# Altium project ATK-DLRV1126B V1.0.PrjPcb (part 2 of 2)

## Sheet 11_ATK_RV1126B_TYPEC_USB30.SchDoc
size A4; Author: ALIENTEK; Revision: 0; SheetNumber: 11; SheetTotal: 13; Version: V1.0; SheetSize: A4
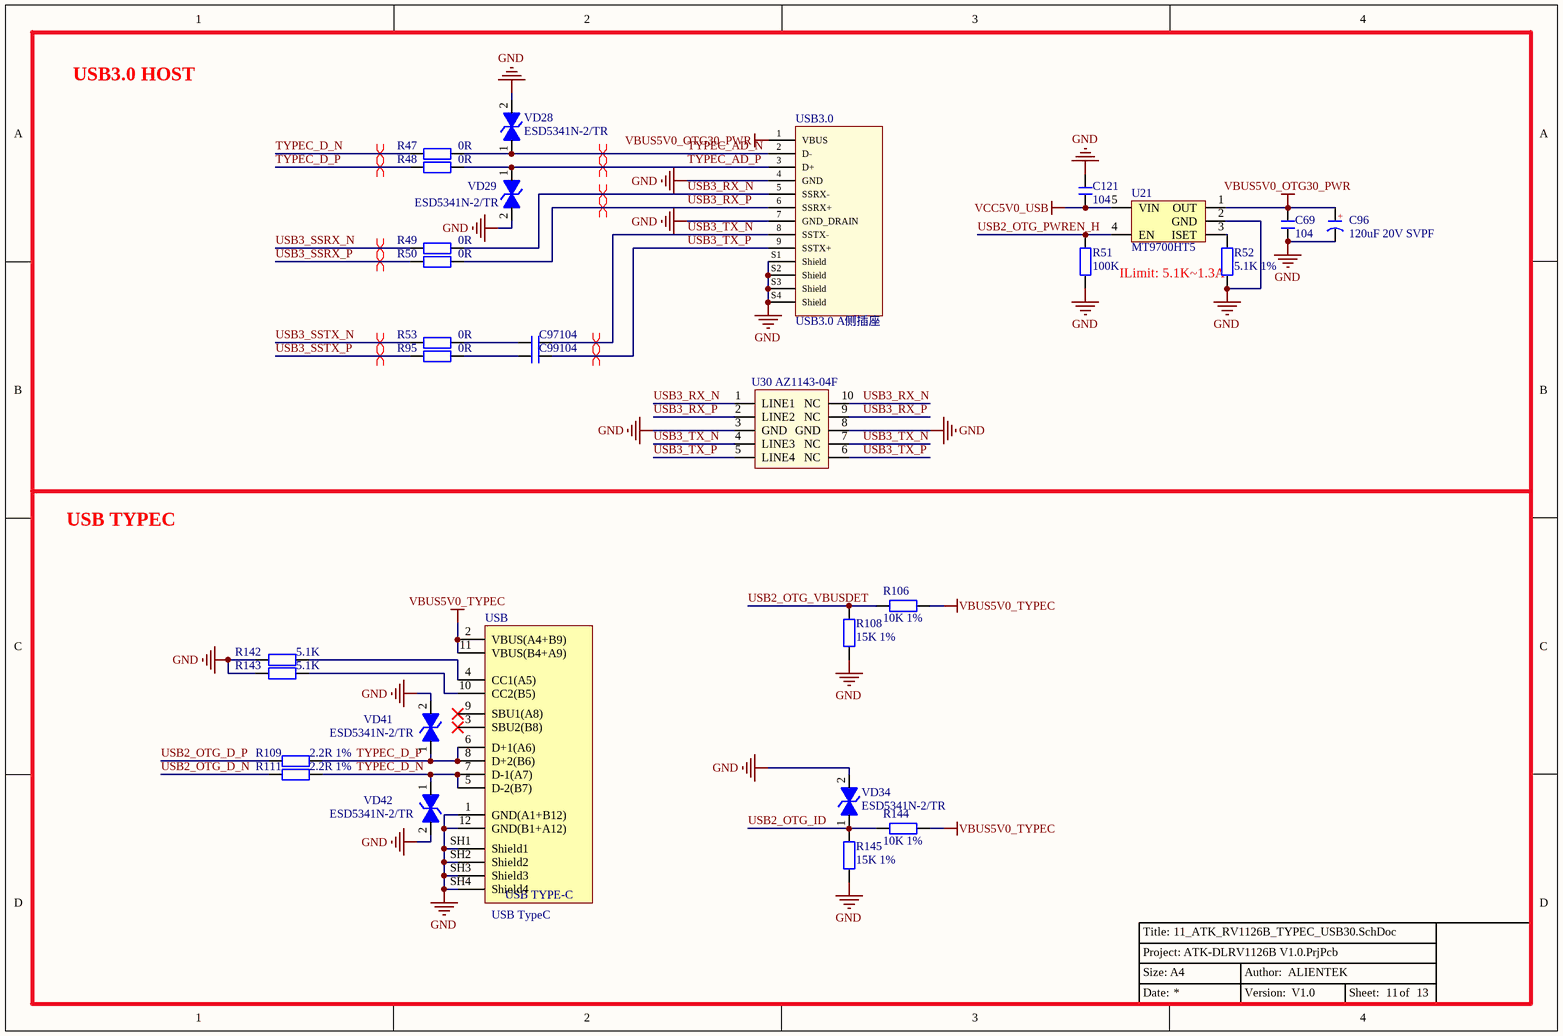
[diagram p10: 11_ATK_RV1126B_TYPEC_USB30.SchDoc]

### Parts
C69  104  [C 0402]
C96  120uF 20V SVPF  [CM D(6.3*7.7)]
C97  104  [C 0402]
C99  104  [C 0402]
C121  104  [C 0402]
R47  0R  [R 0402]
R48  0R  [R 0402]
R49  0R  [R 0402]
R50  0R  [R 0402]
R51  100K  [R 0402]
R52  5.1K 1%  [R 0402]
R53  0R  [R 0402]
R95  0R  [R 0402]
R106  10K 1%  [R 0402]
R108  15K 1%  [R 0402]
R109  2.2R 1%  [R 0402]
R111  2.2R 1%  [R 0402]
R142  5.1K  [R 0402]
R143  5.1K  [R 0402]
R144  10K 1%  [R 0402]
R145  15K 1%  [R 0402]
U21  MT9700HT5  [SOT23-5N]
U30  AZ1143-04F  [DFN2510P10E]
USB  USB TypeC  [USB2.0-TYPE-C-16P]
USB3.0  USB3.0 A侧插座  [USB3.0 A侧插]
VD28  ESD5341N-2/TR  [ESD0402]
VD29  ESD5341N-2/TR  [ESD0402]
VD34  ESD5341N-2/TR  [ESD0402]
VD41  ESD5341N-2/TR  [ESD0402]
VD42  ESD5341N-2/TR  [ESD0402]

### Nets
GND: C69.2 C96.2(K) C121.1 R51.2 R52.2 R108.2 R142.1 R143.1 R145.2 U21.2(GND) U30.3(GND) U30.8(GND) USB.1(GND(A1+B12)) USB.12(GND(B1+A12)) USB.SH1(Shield1) USB.SH2(Shield2) USB.SH3(Shield3) USB.SH4(Shield4) USB3.0.4(GND) USB3.0.7(GND_DRAIN) USB3.0.S1(Shield) USB3.0.S2(Shield) USB3.0.S3(Shield) USB3.0.S4(Shield) VD28.2 VD29.2 VD34.2 VD41.2 VD42.2
VBUS5V0_OTG30_PWR: C69.1 C96.1(A) U21.1(OUT) USB3.0.1(VBUS)
VBUS5V0_TYPEC: R106.1 R144.1 USB.2(VBUS(A4+B9)) USB.11(VBUS(B4+A9))
VCC5V0_USB: C121.2 U21.5(VIN)
TYPEC_AD_N: R47.1 USB3.0.2(D-) VD28.1
TYPEC_AD_P: R48.1 USB3.0.3(D+) VD29.1
TYPEC_D_N: R47.2 R111.1 USB.5(D-2(B7)) USB.7(D-1(A7)) VD42.1
TYPEC_D_P: R48.2 R109.1 USB.6(D+1(A6)) USB.8(D+2(B6)) VD41.1
USB2_OTG_D_N: R111.2
USB2_OTG_D_P: R109.2
USB2_OTG_ID: R144.2 R145.1 VD34.1
USB2_OTG_PWREN_H: R51.1 U21.4(EN)  [project net GPIO5_A7]
USB2_OTG_VBUSDET: R106.2 R108.1
USB3_RX_N: R49.1 U30.1(LINE1) U30.10(NC) USB3.0.5(SSRX-)
USB3_RX_P: R50.1 U30.2(LINE2) U30.9(NC) USB3.0.6(SSRX+)
USB3_SSRX_N: R49.2
USB3_SSRX_P: R50.2
USB3_SSTX_N: R53.2
USB3_SSTX_P: R95.2
USB3_TX_N: C97.2 U30.4(LINE3) U30.7(NC) USB3.0.8(SSTX-)
USB3_TX_P: C99.2 U30.5(LINE4) U30.6(NC) USB3.0.9(SSTX+)
NetC97_1: C97.1 R53.1
NetC99_1: C99.1 R95.1
NetR52_1: R52.1 U21.3(ISET)
NetR142_2: R142.2 USB.4(CC1(A5))
NetR143_2: R143.2 USB.10(CC2(B5))

Not connected (* = marked no-connect by the designer): USB 3(SBU2(B8))* 9(SBU1(A8))*

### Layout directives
differential pair: TYPEC_AD_N, TYPEC_AD_P, TYPEC_D_N, TYPEC_D_P, USB3_RX_N, USB3_RX_P, USB3_SSRX_N, USB3_SSRX_P, USB3_SSTX_N, USB3_SSTX_P, USB3_TX_N, USB3_TX_P

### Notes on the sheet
- USB3.0 HOST
- (near R52) ILimit: 5.1K
  .3A
- USB TYPEC

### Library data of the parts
C69 C97 C99 C121 = C: 无极性贴片电容; 版权归属: 源创客
C96 = C-CM: 贴片电解电容; 版权归属: 源创客
R47-R53 R95 R106 R108 R109 R111 R142-R145 = R: 贴片电阻; BOM名称: 电阻; 版权归属: 正点原子
U21 = MT9700HT5: 功率开关(5.5V-2A); BOM名称: 稳压芯片; 版权归属: 正点原子
U30 = AZ1143-04F: ESD保护二极管阵列
USB = USB Type-C: 12P TypeC 母座; 版权归属: 正点原子; Parameter: 接口器件
USB3.0 = USB3.0 A侧插
VD28 VD29 VD34 VD41 VD42 = ESD5341N: ESD二极管-单向

## Sheet 12_ATK_RV1126B_CSI_DSI.SchDoc
size A4; Author: ALIENTEK; Revision: 0; SheetNumber: 12; SheetTotal: 13; Version: V1.0; SheetSize: A4
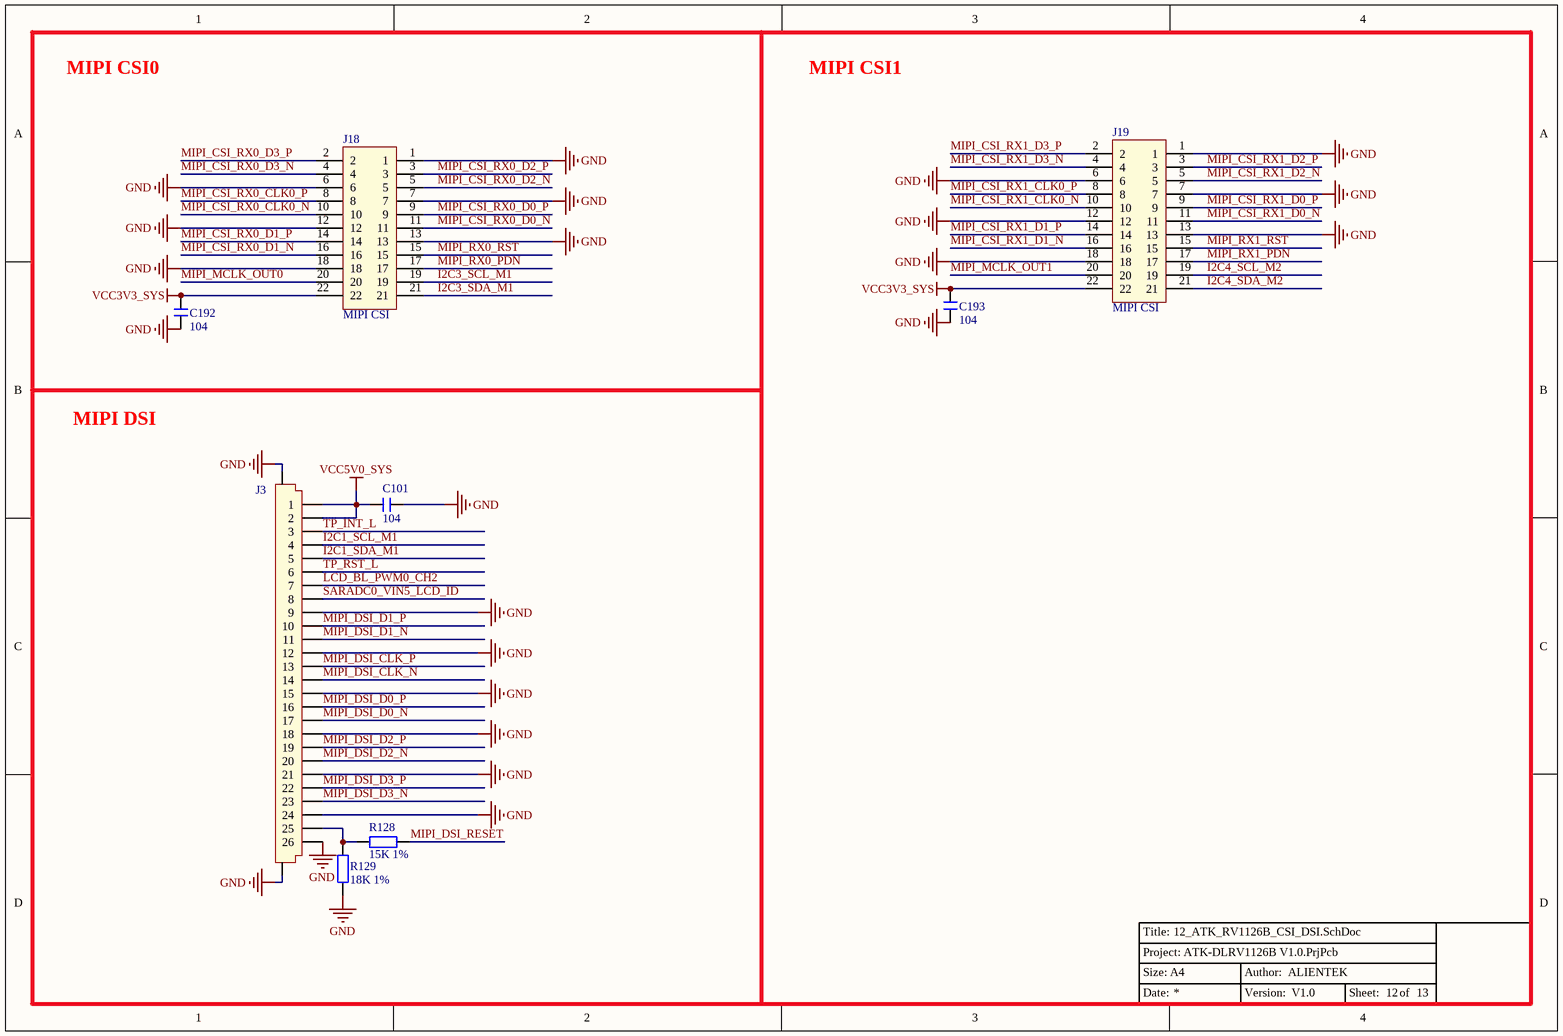
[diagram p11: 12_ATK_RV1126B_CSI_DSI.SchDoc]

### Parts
C101  104  [C 0402]
C192  104  [C 0402]
C193  104  [C 0402]
J3  FPC0.5-26P  [FPC 0.5 26P V-S]  (value not drawn)
J18  MIPI CSI  [HEADER 2.0 2X11P]
J19  MIPI CSI  [HEADER 2.0 2X11P]
R128  15K 1%  [R 0402]
R129  18K 1%  [R 0402]

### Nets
GND: C101.1 C192.1 C193.1 J3.0 J3.9 J3.12 J3.15 J3.18 J3.21 J3.24 J3.26 J18.1 J18.6 J18.7 J18.12 J18.13 J18.18 J19.1 J19.6 J19.7 J19.12 J19.13 J19.18 R129.1
VCC3V3_SYS: C192.2 C193.2 J18.22 J19.22
VCC5V0_SYS: C101.2 J3.1 J3.2
I2C1_SCL_M1: J3.4  [project net GPIO3_A2]
I2C1_SDA_M1: J3.5  [project net GPIO3_A3]
I2C3_SCL_M1: J18.19  [project net GPIO4_A4]
I2C3_SDA_M1: J18.21  [project net GPIO4_A5]
I2C4_SCL_M2: J19.19  [project net GPIO4_A7]
I2C4_SDA_M2: J19.21  [project net GPIO4_A6]
LCD_BL_PWM0_CH2: J3.7  [project net GPIO0_C6]
MIPI_CSI_RX0_CLK0_N: J18.10
MIPI_CSI_RX0_CLK0_P: J18.8
MIPI_CSI_RX0_D0_N: J18.11
MIPI_CSI_RX0_D0_P: J18.9
MIPI_CSI_RX0_D1_N: J18.16
MIPI_CSI_RX0_D1_P: J18.14
MIPI_CSI_RX0_D2_N: J18.5
MIPI_CSI_RX0_D2_P: J18.3
MIPI_CSI_RX0_D3_N: J18.4
MIPI_CSI_RX0_D3_P: J18.2
MIPI_CSI_RX1_CLK0_N: J19.10
MIPI_CSI_RX1_CLK0_P: J19.8
MIPI_CSI_RX1_D0_N: J19.11
MIPI_CSI_RX1_D0_P: J19.9
MIPI_CSI_RX1_D1_N: J19.16
MIPI_CSI_RX1_D1_P: J19.14
MIPI_CSI_RX1_D2_N: J19.5
MIPI_CSI_RX1_D2_P: J19.3
MIPI_CSI_RX1_D3_N: J19.4
MIPI_CSI_RX1_D3_P: J19.2
MIPI_DSI_CLK_N: J3.14
MIPI_DSI_CLK_P: J3.13
MIPI_DSI_D0_N: J3.17
MIPI_DSI_D0_P: J3.16
MIPI_DSI_D1_N: J3.11
MIPI_DSI_D1_P: J3.10
MIPI_DSI_D2_N: J3.20
MIPI_DSI_D2_P: J3.19
MIPI_DSI_D3_N: J3.23
MIPI_DSI_D3_P: J3.22
MIPI_DSI_RESET: R128.2  [project net GPIO7_A7]
MIPI_MCLK_OUT0: J18.20  [project net GPIO4_B1]
MIPI_MCLK_OUT1: J19.20  [project net GPIO4_B0]
MIPI_RX0_PDN: J18.17  [project net GPIO4_A2]
MIPI_RX0_RST: J18.15  [project net GPIO4_A0]
MIPI_RX1_PDN: J19.17  [project net GPIO4_A3]
MIPI_RX1_RST: J19.15  [project net GPIO4_A1]
SARADC0_VIN5_LCD_ID: J3.8
TP_INT_L: J3.3  [project net GPIO3_B3]
TP_RST_L: J3.6  [project net GPIO0_B2]
NetJ3_25: J3.25 R128.1 R129.2

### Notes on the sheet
- MIPI CSI0
- MIPI CSI1
- MIPI DSI

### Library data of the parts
C101 C192 C193 = C: 无极性贴片电容; 版权归属: 正点原子
J3 = FPC-26P: FPC连接器; 版权归属: 正点原子; Parameter: 接口器件
J18 J19 = HEADER 2X11P
R128 R129 = R: 贴片电阻; 版权归属: 正点原子

## Sheet 13_ATK_RV1126B_WIFI_CIF_PIN.SchDoc
size A4; Author: ALIENTEK; Revision: 0; SheetNumber: 13; SheetTotal: 13; Version: V1.0; SheetSize: A4
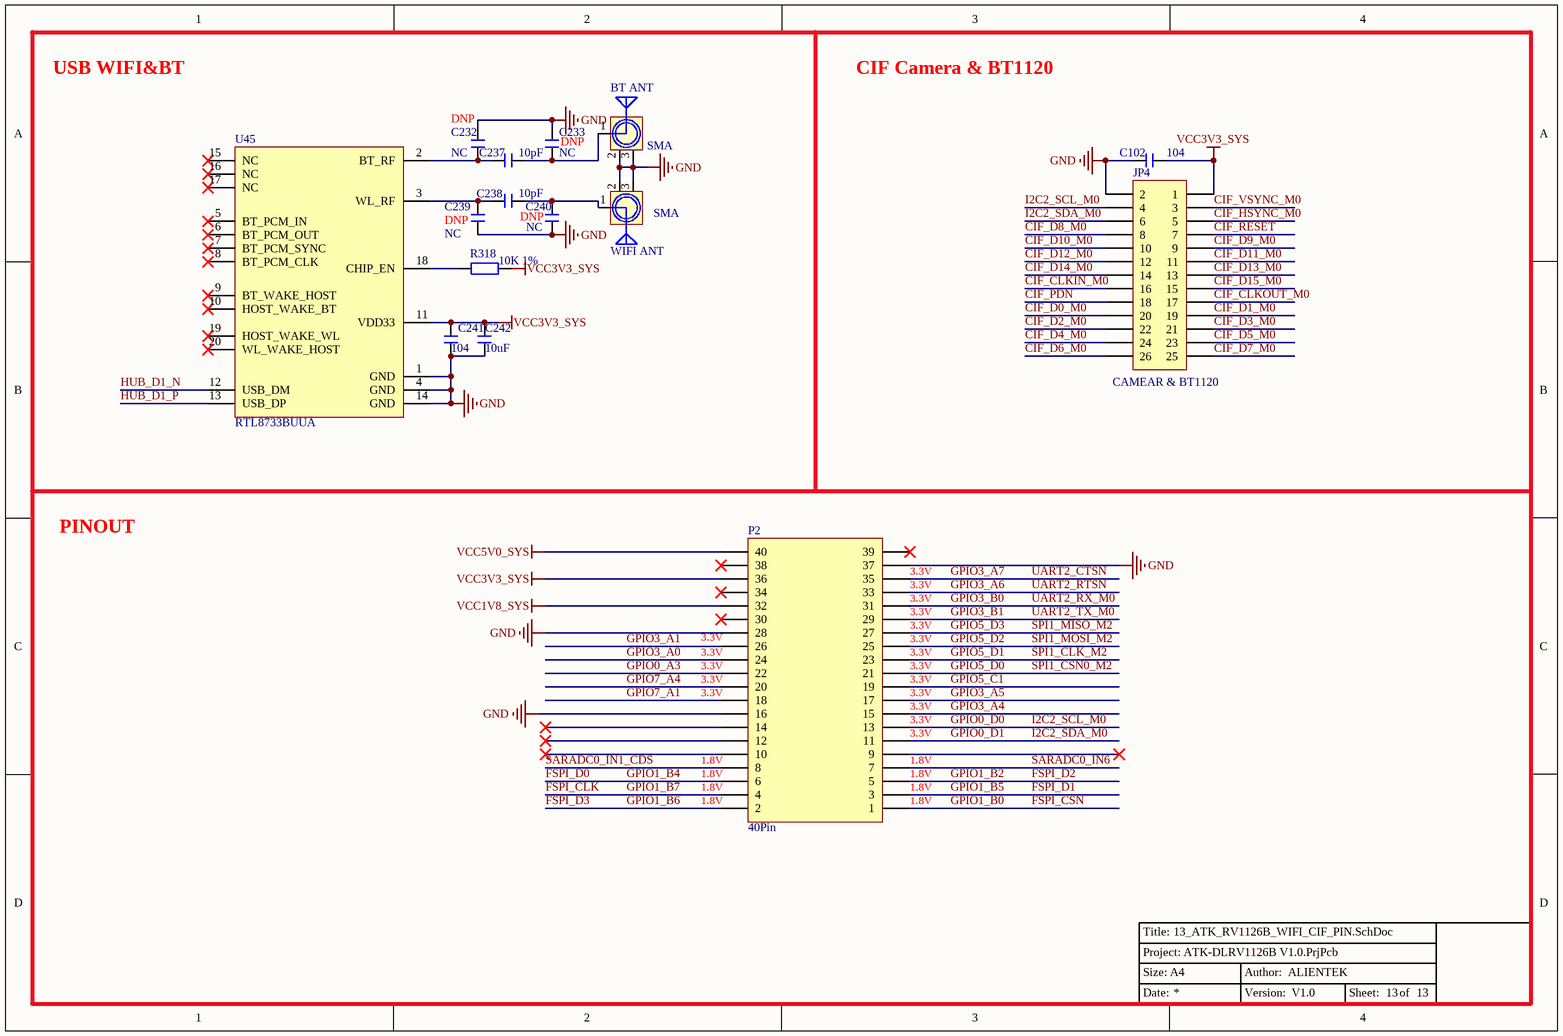
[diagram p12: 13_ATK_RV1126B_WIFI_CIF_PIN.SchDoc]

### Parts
BT_ANT  SMA  [SMA-KWE]
C102  104  [C 0402]
C232  NC  [C 0603]
C233  NC  [C 0603]
C237  10pF  [C 0402]
C238  10pF  [C 0402]
C239  NC  [C 0603]
C240  NC  [C 0603]
C241  104  [C 0402]
C242  10uF  [C 0603]
JP4  CAMEAR & BT1120  [Header 2.54 2X13P]
P2  40Pin  [HDR-20X2]
R318  10K 1%  [R 0402]
U45  RTL8733BUUA  [RTL8733BUBUA]
WIFI_ANT  SMA  [SMA-KWE]

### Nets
GND: BT_ANT.2(GND) BT_ANT.3(GND) C102.1 C232.1 C233.1 C239.2 C240.2 C241.2 C242.2 JP4.2 P2.16 P2.28 P2.37 U45.1(GND) U45.4(GND) U45.14(GND) WIFI_ANT.2(GND) WIFI_ANT.3(GND)
VCC1V8_SYS: P2.32
VCC3V3_SYS: C102.2 C241.1 C242.1 JP4.1 P2.36 R318.1 U45.11(VDD33)
VCC5V0_SYS: P2.40
CIF_CLKIN_M0: JP4.16
CIF_CLKOUT_M0: JP4.17
CIF_D0_M0: JP4.20
CIF_D1_M0: JP4.19
CIF_D2_M0: JP4.22
CIF_D3_M0: JP4.21
CIF_D4_M0: JP4.24
CIF_D5_M0: JP4.23
CIF_D6_M0: JP4.26
CIF_D7_M0: JP4.25
CIF_D8_M0: JP4.8
CIF_D9_M0: JP4.9
CIF_D10_M0: JP4.10
CIF_D11_M0: JP4.11
CIF_D12_M0: JP4.12
CIF_D13_M0: JP4.13
CIF_D14_M0: JP4.14
CIF_D15_M0: JP4.15
CIF_HSYNC_M0: JP4.5
CIF_PDN: JP4.18
CIF_RESET: JP4.7
CIF_VSYNC_M0: JP4.3
FSPI_CLK: P2.4  [also labelled GPIO1_B7]
FSPI_CSN: P2.1  [also labelled GPIO1_B0]
FSPI_D0: P2.6  [also labelled GPIO1_B4]
FSPI_D1: P2.3  [also labelled GPIO1_B5]
FSPI_D2: P2.5  [also labelled GPIO1_B2]
FSPI_D3: P2.2  [also labelled GPIO1_B6]
GPIO0_A3: P2.22
GPIO0_D0: JP4.4 P2.13  [also labelled I2C2_SCL_M0]
GPIO0_D1: JP4.6 P2.11  [also labelled I2C2_SDA_M0]
GPIO3_A0: P2.24
GPIO3_A1: P2.26
GPIO3_A4: P2.15
GPIO3_A5: P2.17
GPIO3_A6: P2.33  [also labelled UART2_RTSN]
GPIO3_A7: P2.35  [also labelled UART2_CTSN]
GPIO3_B0: P2.31  [also labelled UART2_RX_M0]
GPIO3_B1: P2.29  [also labelled UART2_TX_M0]
GPIO5_C1: P2.19  [project net CLK_OUT_ETHERNET]
GPIO5_D0: P2.21  [also labelled SPI1_CSN0_M2]  [project net GMAC_PTP_REFCLK]
GPIO5_D1: P2.23  [also labelled SPI1_CLK_M2]  [project net GMAC_PPSTRIG]
GPIO5_D2: P2.25  [also labelled SPI1_MOSI_M2]
GPIO5_D3: P2.27  [also labelled SPI1_MISO_M2]
GPIO7_A1: P2.18
GPIO7_A4: P2.20
HUB_D1_N: U45.12(USB_DM)
HUB_D1_P: U45.13(USB_DP)
SARADC0_IN1_CDS: P2.8
SARADC0_IN6: P2.7
NetBT_ANT_1: BT_ANT.1(ANT) C233.2 C237.1
NetC232_2: C232.2 C237.2 U45.2(BT_RF)
NetC238_1: C238.1 C240.1 WIFI_ANT.1(ANT)
NetC238_2: C238.2 C239.1 U45.3(WL_RF)
NetR318_2: R318.2 U45.18(CHIP_EN)

Not connected (* = marked no-connect by the designer): P2 9* 10* 12* 14* 30* 34* 38* 39*; U45 5(BT_PCM_IN)* 6(BT_PCM_OUT)* 7(BT_PCM_SYNC)* 8(BT_PCM_CLK)* 9(BT_WAKE_HOST)* 10(HOST_WAKE_BT)* 15(NC)* 16(NC)* 17(NC)* 19(HOST_WAKE_WL)* 20(WL_WAKE_HOST)*

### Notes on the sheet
- USB WIFI&BT
- CIF Camera & BT1120
- (near C232) DNP
- (near C233) DNP
- (near C239) DNP
- DNP
- PINOUT
- (near P2) 3.3V
- (near P2) 1.8V

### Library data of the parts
BT_ANT WIFI_ANT = SMA: SMA-2.4G射频天线接口; 版权归属: 正点原子
C102 C232 C233 C237-C242 = C: 无极性贴片电容; 版权归属: 源创客
JP4 = Header 13X2: Header, 13-Pin, Dual row
P2 = RPI40Pin
R318 = R: 贴片电阻; 版权归属: 正点原子

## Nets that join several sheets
GND: 02_ATK_RV1126B_Core_Board (55 pins), 03_ATK_RV1126B_Power_USB (67 pins), 04_ATK_RV1126B_4G_USBHUB (47 pins), 05_ATK_RV1126B_DEVICE (31 pins), 06_ATK_RV1126B_ES8390_Audio (49 pins), 08_ATK_RV1126B_RS485_CAN (21 pins), 09_ATK_RV1126B_RGMII_NET (35 pins), 10_ATK_RV1126B_FEPHY_NET_OPT (18 pins), 11_ATK_RV1126B_TYPEC_USB30 (29 pins), 12_ATK_RV1126B_CSI_DSI (24 pins), 13_ATK_RV1126B_WIFI_CIF_PIN (18 pins)
VBAT: 03_ATK_RV1126B_Power_USB (BAT.1 C2.1 L1.2), 05_ATK_RV1126B_DEVICE (L10.2)
VBAT_RTC: 02_ATK_RV1126B_Core_Board (U1.A114), 03_ATK_RV1126B_Power_USB (L1.1)
VCC1V8_SYS: 03_ATK_RV1126B_Power_USB (C26.1 C27.1 L3.2 R27.2), 05_ATK_RV1126B_DEVICE (5 pins), 13_ATK_RV1126B_WIFI_CIF_PIN (P2.32)
VCC3V3_SYS: 03_ATK_RV1126B_Power_USB (12 pins), 05_ATK_RV1126B_DEVICE (12 pins), 08_ATK_RV1126B_RS485_CAN (18 pins), 09_ATK_RV1126B_RGMII_NET (L19.2 L20.2), 12_ATK_RV1126B_CSI_DSI (C192.2 C193.2 J18.22 J19.22), 13_ATK_RV1126B_WIFI_CIF_PIN (7 pins)
VCC5V0_SYS: 02_ATK_RV1126B_Core_Board (U1.A117 U1.A118 U1.A119 U1.A120), 03_ATK_RV1126B_Power_USB (8 pins), 06_ATK_RV1126B_ES8390_Audio (C14.1 L12.1 R11.1 U15.1), 08_ATK_RV1126B_RS485_CAN (5 pins), 12_ATK_RV1126B_CSI_DSI (C101.2 J3.1 J3.2), 13_ATK_RV1126B_WIFI_CIF_PIN (P2.40)
VCC5V0_USB: 03_ATK_RV1126B_Power_USB (5 pins), 04_ATK_RV1126B_4G_USBHUB (L6.2 USB_HOST1.1 USB_HOST2.1), 11_ATK_RV1126B_TYPEC_USB30 (C121.2 U21.5)
VCC12V_DCIN: 03_ATK_RV1126B_Power_USB (23 pins), 04_ATK_RV1126B_4G_USBHUB (C57.2 C58.2 R54.1 U10.3), 08_ATK_RV1126B_RS485_CAN (FAN.2)
CAN0_RXD: 02_ATK_RV1126B_Core_Board (U1.A94), 08_ATK_RV1126B_RS485_CAN (R23.2)
CAN0_TXD: 02_ATK_RV1126B_Core_Board (U1.A93), 08_ATK_RV1126B_RS485_CAN (R21.2)
CAN1_RXD: 02_ATK_RV1126B_Core_Board (U1.A90), 08_ATK_RV1126B_RS485_CAN (R45.2)
CAN1_TXD: 02_ATK_RV1126B_Core_Board (U1.A91), 08_ATK_RV1126B_RS485_CAN (R39.2)
CIF_CLKIN_M0: 02_ATK_RV1126B_Core_Board (U1.B5), 13_ATK_RV1126B_WIFI_CIF_PIN (JP4.16)
CIF_CLKOUT_M0: 02_ATK_RV1126B_Core_Board (U1.B3), 13_ATK_RV1126B_WIFI_CIF_PIN (JP4.17)
CIF_D0_M0: 02_ATK_RV1126B_Core_Board (U1.B22), 13_ATK_RV1126B_WIFI_CIF_PIN (JP4.20)
CIF_D1_M0: 02_ATK_RV1126B_Core_Board (U1.B21), 13_ATK_RV1126B_WIFI_CIF_PIN (JP4.19)
CIF_D2_M0: 02_ATK_RV1126B_Core_Board (U1.B20), 13_ATK_RV1126B_WIFI_CIF_PIN (JP4.22)
CIF_D3_M0: 02_ATK_RV1126B_Core_Board (U1.B19), 13_ATK_RV1126B_WIFI_CIF_PIN (JP4.21)
CIF_D4_M0: 02_ATK_RV1126B_Core_Board (U1.B18), 13_ATK_RV1126B_WIFI_CIF_PIN (JP4.24)
CIF_D5_M0: 02_ATK_RV1126B_Core_Board (U1.B17), 13_ATK_RV1126B_WIFI_CIF_PIN (JP4.23)
CIF_D6_M0: 02_ATK_RV1126B_Core_Board (U1.B16), 13_ATK_RV1126B_WIFI_CIF_PIN (JP4.26)
CIF_D7_M0: 02_ATK_RV1126B_Core_Board (U1.B15), 13_ATK_RV1126B_WIFI_CIF_PIN (JP4.25)
CIF_D8_M0: 02_ATK_RV1126B_Core_Board (U1.B14), 13_ATK_RV1126B_WIFI_CIF_PIN (JP4.8)
CIF_D9_M0: 02_ATK_RV1126B_Core_Board (U1.B13), 13_ATK_RV1126B_WIFI_CIF_PIN (JP4.9)
CIF_D10_M0: 02_ATK_RV1126B_Core_Board (U1.B12), 13_ATK_RV1126B_WIFI_CIF_PIN (JP4.10)
CIF_D11_M0: 02_ATK_RV1126B_Core_Board (U1.B11), 13_ATK_RV1126B_WIFI_CIF_PIN (JP4.11)
CIF_D12_M0: 02_ATK_RV1126B_Core_Board (U1.B10), 13_ATK_RV1126B_WIFI_CIF_PIN (JP4.12)
CIF_D13_M0: 02_ATK_RV1126B_Core_Board (U1.B9), 13_ATK_RV1126B_WIFI_CIF_PIN (JP4.13)
CIF_D14_M0: 02_ATK_RV1126B_Core_Board (U1.B8), 13_ATK_RV1126B_WIFI_CIF_PIN (JP4.14)
CIF_D15_M0: 02_ATK_RV1126B_Core_Board (U1.B7), 13_ATK_RV1126B_WIFI_CIF_PIN (JP4.15)
CIF_HSYNC_M0: 02_ATK_RV1126B_Core_Board (U1.B2), 13_ATK_RV1126B_WIFI_CIF_PIN (JP4.5)
CIF_PDN: 02_ATK_RV1126B_Core_Board (U1.B54), 13_ATK_RV1126B_WIFI_CIF_PIN (JP4.18)
CIF_RESET: 02_ATK_RV1126B_Core_Board (U1.A36), 13_ATK_RV1126B_WIFI_CIF_PIN (JP4.7)
CIF_VSYNC_M0: 02_ATK_RV1126B_Core_Board (U1.B6), 13_ATK_RV1126B_WIFI_CIF_PIN (JP4.3)
CLK_OUT_ETHERNET: 02_ATK_RV1126B_Core_Board (U1.A27), 13_ATK_RV1126B_WIFI_CIF_PIN (P2.19)
FSPI_CLK: 02_ATK_RV1126B_Core_Board (U1.A63), 13_ATK_RV1126B_WIFI_CIF_PIN (P2.4)
FSPI_CSN: 02_ATK_RV1126B_Core_Board (U1.A57), 13_ATK_RV1126B_WIFI_CIF_PIN (P2.1)
FSPI_D0: 02_ATK_RV1126B_Core_Board (U1.A62), 13_ATK_RV1126B_WIFI_CIF_PIN (P2.6)
FSPI_D1: 02_ATK_RV1126B_Core_Board (U1.A58), 13_ATK_RV1126B_WIFI_CIF_PIN (P2.3)
FSPI_D2: 02_ATK_RV1126B_Core_Board (U1.A59), 13_ATK_RV1126B_WIFI_CIF_PIN (P2.5)
FSPI_D3: 02_ATK_RV1126B_Core_Board (U1.A64), 13_ATK_RV1126B_WIFI_CIF_PIN (P2.2)
GMAC_INT: 02_ATK_RV1126B_Core_Board (U1.A8), 09_ATK_RV1126B_RGMII_NET (R46.1)
GMAC_MCLK: 02_ATK_RV1126B_Core_Board (U1.A7), 09_ATK_RV1126B_RGMII_NET (R191.1)
GMAC_MDC: 02_ATK_RV1126B_Core_Board (U1.A25), 09_ATK_RV1126B_RGMII_NET (R185.1)
GMAC_MDIO: 02_ATK_RV1126B_Core_Board (U1.A24), 09_ATK_RV1126B_RGMII_NET (R184.1)
GMAC_PPSCLK: 02_ATK_RV1126B_Core_Board (U1.A32), 08_ATK_RV1126B_RS485_CAN (P1.3)
GMAC_PPSTRIG: 02_ATK_RV1126B_Core_Board (U1.A29), 13_ATK_RV1126B_WIFI_CIF_PIN (P2.23)
GMAC_PTP_REFCLK: 02_ATK_RV1126B_Core_Board (U1.A28), 13_ATK_RV1126B_WIFI_CIF_PIN (P2.21)
GMAC_RST: 02_ATK_RV1126B_Core_Board (U1.A26), 09_ATK_RV1126B_RGMII_NET (R187.1)
GMAC_RXCLK: 02_ATK_RV1126B_Core_Board (U1.A10), 09_ATK_RV1126B_RGMII_NET (R177.2)
GMAC_RXCTL: 02_ATK_RV1126B_Core_Board (U1.A11), 09_ATK_RV1126B_RGMII_NET (R178.2)
GMAC_RXD0: 02_ATK_RV1126B_Core_Board (U1.A12), 09_ATK_RV1126B_RGMII_NET (R171.2)
GMAC_RXD1: 02_ATK_RV1126B_Core_Board (U1.A13), 09_ATK_RV1126B_RGMII_NET (R172.2)
GMAC_RXD2: 02_ATK_RV1126B_Core_Board (U1.A14), 09_ATK_RV1126B_RGMII_NET (R173.2)
GMAC_RXD3: 02_ATK_RV1126B_Core_Board (U1.A15), 09_ATK_RV1126B_RGMII_NET (R174.2)
GMAC_TXCLK: 02_ATK_RV1126B_Core_Board (U1.A17), 09_ATK_RV1126B_RGMII_NET (U23.20)
GMAC_TXCTL: 02_ATK_RV1126B_Core_Board (U1.A19), 09_ATK_RV1126B_RGMII_NET (U23.19)
GMAC_TXD0: 02_ATK_RV1126B_Core_Board (U1.A20), 09_ATK_RV1126B_RGMII_NET (U23.18)
GMAC_TXD1: 02_ATK_RV1126B_Core_Board (U1.A21), 09_ATK_RV1126B_RGMII_NET (U23.17)
GMAC_TXD2: 02_ATK_RV1126B_Core_Board (U1.A22), 09_ATK_RV1126B_RGMII_NET (U23.16)
GMAC_TXD3: 02_ATK_RV1126B_Core_Board (U1.A23), 09_ATK_RV1126B_RGMII_NET (U23.15)
GPIO0_A0: 02_ATK_RV1126B_Core_Board (U1.B50), 06_ATK_RV1126B_ES8390_Audio (R57.1 U13.1 U14.1)
GPIO0_A2: 02_ATK_RV1126B_Core_Board (U1.B51), 06_ATK_RV1126B_ES8390_Audio (R343.1)
GPIO0_A3: 02_ATK_RV1126B_Core_Board (U1.B61), 13_ATK_RV1126B_WIFI_CIF_PIN (P2.22)
GPIO0_A4: 02_ATK_RV1126B_Core_Board (U1.B57), 06_ATK_RV1126B_ES8390_Audio (C88.1 PHONE.7 R79.2 VD12.1)
GPIO0_A5: 02_ATK_RV1126B_Core_Board (U1.B31), 05_ATK_RV1126B_DEVICE (R92.2)
GPIO0_B0: 02_ATK_RV1126B_Core_Board (U1.B30), 05_ATK_RV1126B_DEVICE (R89.1)
GPIO0_B1: 02_ATK_RV1126B_Core_Board (U1.B59), 05_ATK_RV1126B_DEVICE (R17.2 U17.3)
GPIO0_B2: 02_ATK_RV1126B_Core_Board (U1.B60), 12_ATK_RV1126B_CSI_DSI (J3.6)
GPIO0_B3: 02_ATK_RV1126B_Core_Board (U1.B48), 03_ATK_RV1126B_Power_USB (R44.2)
GPIO0_B4: 02_ATK_RV1126B_Core_Board (U1.B49), 03_ATK_RV1126B_Power_USB (R81.2 R101.1)
GPIO0_C5: 02_ATK_RV1126B_Core_Board (U1.B53), 05_ATK_RV1126B_DEVICE (R113.2)
GPIO0_C6: 02_ATK_RV1126B_Core_Board (U1.B52), 12_ATK_RV1126B_CSI_DSI (J3.7)
GPIO0_D0: 02_ATK_RV1126B_Core_Board (U1.A103), 05_ATK_RV1126B_DEVICE (R100.2 U17.6), 13_ATK_RV1126B_WIFI_CIF_PIN (JP4.4 P2.13)
GPIO0_D1: 02_ATK_RV1126B_Core_Board (U1.A102), 05_ATK_RV1126B_DEVICE (R102.2 U17.5), 13_ATK_RV1126B_WIFI_CIF_PIN (JP4.6 P2.11)
GPIO2_A0: 02_ATK_RV1126B_Core_Board (U1.B33), 05_ATK_RV1126B_DEVICE (R90.2)
GPIO2_A1: 02_ATK_RV1126B_Core_Board (U1.B32), 05_ATK_RV1126B_DEVICE (R91.2)
GPIO2_A2: 02_ATK_RV1126B_Core_Board (U1.B37), 05_ATK_RV1126B_DEVICE (R83.2)
GPIO2_A3: 02_ATK_RV1126B_Core_Board (U1.B36), 05_ATK_RV1126B_DEVICE (R84.2)
GPIO2_A4: 02_ATK_RV1126B_Core_Board (U1.B34), 05_ATK_RV1126B_DEVICE (R86.2)
GPIO2_A5: 02_ATK_RV1126B_Core_Board (U1.B35), 05_ATK_RV1126B_DEVICE (R85.2)
GPIO3_A0: 02_ATK_RV1126B_Core_Board (U1.A46), 13_ATK_RV1126B_WIFI_CIF_PIN (P2.24)
GPIO3_A1: 02_ATK_RV1126B_Core_Board (U1.A47), 13_ATK_RV1126B_WIFI_CIF_PIN (P2.26)
GPIO3_A2: 02_ATK_RV1126B_Core_Board (U1.A45), 05_ATK_RV1126B_DEVICE (R15.2), 12_ATK_RV1126B_CSI_DSI (J3.4)
GPIO3_A3: 02_ATK_RV1126B_Core_Board (U1.A44), 05_ATK_RV1126B_DEVICE (R16.2), 12_ATK_RV1126B_CSI_DSI (J3.5)
GPIO3_A4: 02_ATK_RV1126B_Core_Board (U1.A49), 13_ATK_RV1126B_WIFI_CIF_PIN (P2.15)
GPIO3_A5: 02_ATK_RV1126B_Core_Board (U1.A48), 13_ATK_RV1126B_WIFI_CIF_PIN (P2.17)
GPIO3_A6: 02_ATK_RV1126B_Core_Board (U1.A53), 13_ATK_RV1126B_WIFI_CIF_PIN (P2.33)
GPIO3_A7: 02_ATK_RV1126B_Core_Board (U1.A54), 13_ATK_RV1126B_WIFI_CIF_PIN (P2.35)
GPIO3_B0: 02_ATK_RV1126B_Core_Board (U1.A55), 13_ATK_RV1126B_WIFI_CIF_PIN (P2.31)
GPIO3_B1: 02_ATK_RV1126B_Core_Board (U1.A56), 13_ATK_RV1126B_WIFI_CIF_PIN (P2.29)
GPIO3_B2: 02_ATK_RV1126B_Core_Board (U1.A51), 08_ATK_RV1126B_RS485_CAN (MOS3.2 R122.1 R127.2)
GPIO3_B3: 02_ATK_RV1126B_Core_Board (U1.A52), 12_ATK_RV1126B_CSI_DSI (J3.3)
GPIO3_B6: 02_ATK_RV1126B_Core_Board (U1.A97), 05_ATK_RV1126B_DEVICE (R12.2), 06_ATK_RV1126B_ES8390_Audio (R65.2)
GPIO3_B7: 02_ATK_RV1126B_Core_Board (U1.A96), 05_ATK_RV1126B_DEVICE (R13.2), 06_ATK_RV1126B_ES8390_Audio (R66.2)
GPIO4_A0: 02_ATK_RV1126B_Core_Board (U1.B119), 12_ATK_RV1126B_CSI_DSI (J18.15)
GPIO4_A1: 02_ATK_RV1126B_Core_Board (U1.B118), 12_ATK_RV1126B_CSI_DSI (J19.15)
GPIO4_A2: 02_ATK_RV1126B_Core_Board (U1.B114), 12_ATK_RV1126B_CSI_DSI (J18.17)
GPIO4_A3: 02_ATK_RV1126B_Core_Board (U1.B113), 12_ATK_RV1126B_CSI_DSI (J19.17)
GPIO4_A4: 02_ATK_RV1126B_Core_Board (U1.A101), 05_ATK_RV1126B_DEVICE (R104.2), 12_ATK_RV1126B_CSI_DSI (J18.19)
GPIO4_A5: 02_ATK_RV1126B_Core_Board (U1.A100), 05_ATK_RV1126B_DEVICE (R105.2), 12_ATK_RV1126B_CSI_DSI (J18.21)
GPIO4_A6: 02_ATK_RV1126B_Core_Board (U1.A98), 05_ATK_RV1126B_DEVICE (R98.2), 12_ATK_RV1126B_CSI_DSI (J19.21)
GPIO4_A7: 02_ATK_RV1126B_Core_Board (U1.A99), 05_ATK_RV1126B_DEVICE (R97.2), 12_ATK_RV1126B_CSI_DSI (J19.19)
GPIO4_B0: 02_ATK_RV1126B_Core_Board (U1.B117), 12_ATK_RV1126B_CSI_DSI (J19.20)
GPIO4_B1: 02_ATK_RV1126B_Core_Board (U1.B115), 12_ATK_RV1126B_CSI_DSI (J18.20)
GPIO5_A3: 02_ATK_RV1126B_Core_Board (U1.A33), 08_ATK_RV1126B_RS485_CAN (P1.1)
GPIO5_A4: 02_ATK_RV1126B_Core_Board (U1.A34), 08_ATK_RV1126B_RS485_CAN (P1.7)
GPIO5_A5: 02_ATK_RV1126B_Core_Board (U1.A35), 08_ATK_RV1126B_RS485_CAN (P1.5)
GPIO5_A7: 02_ATK_RV1126B_Core_Board (U1.A66), 11_ATK_RV1126B_TYPEC_USB30 (R51.1 U21.4)
GPIO5_D2: 02_ATK_RV1126B_Core_Board (U1.A30), 13_ATK_RV1126B_WIFI_CIF_PIN (P2.25)
GPIO5_D3: 02_ATK_RV1126B_Core_Board (U1.A31), 13_ATK_RV1126B_WIFI_CIF_PIN (P2.27)
GPIO7_A0: 02_ATK_RV1126B_Core_Board (U1.B27), 06_ATK_RV1126B_ES8390_Audio (R61.2)
GPIO7_A1: 02_ATK_RV1126B_Core_Board (U1.B55), 13_ATK_RV1126B_WIFI_CIF_PIN (P2.18)
GPIO7_A2: 02_ATK_RV1126B_Core_Board (U1.B28), 06_ATK_RV1126B_ES8390_Audio (R60.2)
GPIO7_A3: 02_ATK_RV1126B_Core_Board (U1.B25), 06_ATK_RV1126B_ES8390_Audio (R63.2)
GPIO7_A4: 02_ATK_RV1126B_Core_Board (U1.B56), 13_ATK_RV1126B_WIFI_CIF_PIN (P2.20)
GPIO7_A5: 02_ATK_RV1126B_Core_Board (U1.B26), 06_ATK_RV1126B_ES8390_Audio (R62.2)
GPIO7_A6: 02_ATK_RV1126B_Core_Board (U1.B24), 06_ATK_RV1126B_ES8390_Audio (R64.2)
GPIO7_A7: 02_ATK_RV1126B_Core_Board (U1.A65), 12_ATK_RV1126B_CSI_DSI (R128.2)
HUB_D1_N: 04_ATK_RV1126B_4G_USBHUB (U9.7), 13_ATK_RV1126B_WIFI_CIF_PIN (U45.12)
HUB_D1_P: 04_ATK_RV1126B_4G_USBHUB (U9.8), 13_ATK_RV1126B_WIFI_CIF_PIN (U45.13)
MIPI_CSI_RX0_CLK0_N: 02_ATK_RV1126B_Core_Board (U1.B87), 12_ATK_RV1126B_CSI_DSI (J18.10)
MIPI_CSI_RX0_CLK0_P: 02_ATK_RV1126B_Core_Board (U1.B86), 12_ATK_RV1126B_CSI_DSI (J18.8)
MIPI_CSI_RX0_D0_N: 02_ATK_RV1126B_Core_Board (U1.B93), 12_ATK_RV1126B_CSI_DSI (J18.11)
MIPI_CSI_RX0_D0_P: 02_ATK_RV1126B_Core_Board (U1.B92), 12_ATK_RV1126B_CSI_DSI (J18.9)
MIPI_CSI_RX0_D1_N: 02_ATK_RV1126B_Core_Board (U1.B90), 12_ATK_RV1126B_CSI_DSI (J18.16)
MIPI_CSI_RX0_D1_P: 02_ATK_RV1126B_Core_Board (U1.B89), 12_ATK_RV1126B_CSI_DSI (J18.14)
MIPI_CSI_RX0_D2_N: 02_ATK_RV1126B_Core_Board (U1.B78), 12_ATK_RV1126B_CSI_DSI (J18.5)
MIPI_CSI_RX0_D2_P: 02_ATK_RV1126B_Core_Board (U1.B77), 12_ATK_RV1126B_CSI_DSI (J18.3)
MIPI_CSI_RX0_D3_N: 02_ATK_RV1126B_Core_Board (U1.B81), 12_ATK_RV1126B_CSI_DSI (J18.4)
MIPI_CSI_RX0_D3_P: 02_ATK_RV1126B_Core_Board (U1.B80), 12_ATK_RV1126B_CSI_DSI (J18.2)
MIPI_CSI_RX1_CLK0_N: 02_ATK_RV1126B_Core_Board (U1.B105), 12_ATK_RV1126B_CSI_DSI (J19.10)
MIPI_CSI_RX1_CLK0_P: 02_ATK_RV1126B_Core_Board (U1.B104), 12_ATK_RV1126B_CSI_DSI (J19.8)
MIPI_CSI_RX1_D0_N: 02_ATK_RV1126B_Core_Board (U1.B111), 12_ATK_RV1126B_CSI_DSI (J19.11)
MIPI_CSI_RX1_D0_P: 02_ATK_RV1126B_Core_Board (U1.B110), 12_ATK_RV1126B_CSI_DSI (J19.9)
MIPI_CSI_RX1_D1_N: 02_ATK_RV1126B_Core_Board (U1.B108), 12_ATK_RV1126B_CSI_DSI (J19.16)
MIPI_CSI_RX1_D1_P: 02_ATK_RV1126B_Core_Board (U1.B107), 12_ATK_RV1126B_CSI_DSI (J19.14)
MIPI_CSI_RX1_D2_N: 02_ATK_RV1126B_Core_Board (U1.B96), 12_ATK_RV1126B_CSI_DSI (J19.5)
MIPI_CSI_RX1_D2_P: 02_ATK_RV1126B_Core_Board (U1.B95), 12_ATK_RV1126B_CSI_DSI (J19.3)
MIPI_CSI_RX1_D3_N: 02_ATK_RV1126B_Core_Board (U1.B99), 12_ATK_RV1126B_CSI_DSI (J19.4)
MIPI_CSI_RX1_D3_P: 02_ATK_RV1126B_Core_Board (U1.B98), 12_ATK_RV1126B_CSI_DSI (J19.2)
MIPI_DSI_CLK_N: 02_ATK_RV1126B_Core_Board (U1.A81), 12_ATK_RV1126B_CSI_DSI (J3.14)
MIPI_DSI_CLK_P: 02_ATK_RV1126B_Core_Board (U1.A82), 12_ATK_RV1126B_CSI_DSI (J3.13)
MIPI_DSI_D0_N: 02_ATK_RV1126B_Core_Board (U1.A75), 12_ATK_RV1126B_CSI_DSI (J3.17)
MIPI_DSI_D0_P: 02_ATK_RV1126B_Core_Board (U1.A76), 12_ATK_RV1126B_CSI_DSI (J3.16)
MIPI_DSI_D1_N: 02_ATK_RV1126B_Core_Board (U1.A78), 12_ATK_RV1126B_CSI_DSI (J3.11)
MIPI_DSI_D1_P: 02_ATK_RV1126B_Core_Board (U1.A79), 12_ATK_RV1126B_CSI_DSI (J3.10)
MIPI_DSI_D2_N: 02_ATK_RV1126B_Core_Board (U1.A84), 12_ATK_RV1126B_CSI_DSI (J3.20)
MIPI_DSI_D2_P: 02_ATK_RV1126B_Core_Board (U1.A85), 12_ATK_RV1126B_CSI_DSI (J3.19)
MIPI_DSI_D3_N: 02_ATK_RV1126B_Core_Board (U1.A87), 12_ATK_RV1126B_CSI_DSI (J3.23)
MIPI_DSI_D3_P: 02_ATK_RV1126B_Core_Board (U1.A88), 12_ATK_RV1126B_CSI_DSI (J3.22)
PMIC_PWRON: 02_ATK_RV1126B_Core_Board (U1.A110), 05_ATK_RV1126B_DEVICE (R87.1)
RESET: 02_ATK_RV1126B_Core_Board (U1.A108), 05_ATK_RV1126B_DEVICE (R82.1)
SARADC0_IN0_KEY: 02_ATK_RV1126B_Core_Board (U1.A73), 05_ATK_RV1126B_DEVICE (R94.2 R96.1 VD26.1)
SARADC0_IN1_CDS: 02_ATK_RV1126B_Core_Board (U1.A72), 13_ATK_RV1126B_WIFI_CIF_PIN (P2.8)
SARADC0_IN3_HP_HOOK: 02_ATK_RV1126B_Core_Board (U1.A71), 06_ATK_RV1126B_ES8390_Audio (C85.1 R73.2 R75.2)
SARADC0_IN4: 02_ATK_RV1126B_Core_Board (U1.A70), 05_ATK_RV1126B_DEVICE (C17.2 VR.2)
SARADC0_IN6: 02_ATK_RV1126B_Core_Board (U1.A68), 13_ATK_RV1126B_WIFI_CIF_PIN (P2.7)
SARADC0_IN7_BOOT: 02_ATK_RV1126B_Core_Board (U1.A67), 05_ATK_RV1126B_DEVICE (R93.1)
SARADC0_VIN5_LCD_ID: 02_ATK_RV1126B_Core_Board (U1.A69), 12_ATK_RV1126B_CSI_DSI (J3.8)
USB2_HOST_D_N: 02_ATK_RV1126B_Core_Board (U1.B68), 04_ATK_RV1126B_4G_USBHUB (R43.2)
USB2_HOST_D_P: 02_ATK_RV1126B_Core_Board (U1.B69), 04_ATK_RV1126B_4G_USBHUB (R42.2)
USB2_OTG_D_N: 02_ATK_RV1126B_Core_Board (U1.B65), 11_ATK_RV1126B_TYPEC_USB30 (R111.2)
USB2_OTG_D_P: 02_ATK_RV1126B_Core_Board (U1.B66), 11_ATK_RV1126B_TYPEC_USB30 (R109.2)
USB2_OTG_ID: 02_ATK_RV1126B_Core_Board (U1.B63), 11_ATK_RV1126B_TYPEC_USB30 (R144.2 R145.1 VD34.1)
USB2_OTG_VBUSDET: 02_ATK_RV1126B_Core_Board (U1.B62), 11_ATK_RV1126B_TYPEC_USB30 (R106.2 R108.1)
USB3_SSRX_N: 02_ATK_RV1126B_Core_Board (U1.B75), 11_ATK_RV1126B_TYPEC_USB30 (R49.2)
USB3_SSRX_P: 02_ATK_RV1126B_Core_Board (U1.B74), 11_ATK_RV1126B_TYPEC_USB30 (R50.2)
USB3_SSTX_N: 02_ATK_RV1126B_Core_Board (U1.B72), 11_ATK_RV1126B_TYPEC_USB30 (R53.2)
USB3_SSTX_P: 02_ATK_RV1126B_Core_Board (U1.B71), 11_ATK_RV1126B_TYPEC_USB30 (R95.2)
